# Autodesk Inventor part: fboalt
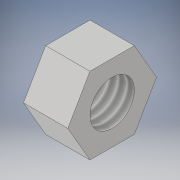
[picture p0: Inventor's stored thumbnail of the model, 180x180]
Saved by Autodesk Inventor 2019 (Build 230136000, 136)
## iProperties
Created: 2020-03
Part Number: fboalt
Material: Generic
Document SubType Name: Modeling
Designer: ash
Density: 1 g/cm^3
Appearance: Default
Author: ash
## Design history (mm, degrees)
sketch "Sketch1"
  geometry: L1 (0, 2)-(1.732, 1); L2 (1.732, 1)-(1.732, -1); L3 (1.732, -1)-(0, -2); L4 (0, -2)-(-1.732, -1); L5 (-1.732, -1)-(-1.732, 1); L6 (-1.732, 1)-(0, 2); 2 further points
  constraints: 12 end point, 1 coincident, 13 other
  dimensions: "d0" = 2 distance of L1.end L2.end
extrude "Extrusion1" new body sketch "Sketch1" distance "d1" = 2; taper "d2" = 0 deg
sketch "Sketch2"
  geometry: C1 r 1 at (0, 0); 1 further point
  constraints: 1 centre point, 1 coincident
  dimensions: "d3" = 2 diameter of C1
extrude "Extrusion2" cut sketch "Sketch2" distance "d4" = 3; taper "d5" = 0 deg
thread "Thread1" dims "d6" = 10, "d7" = 0
body "Solid1"
